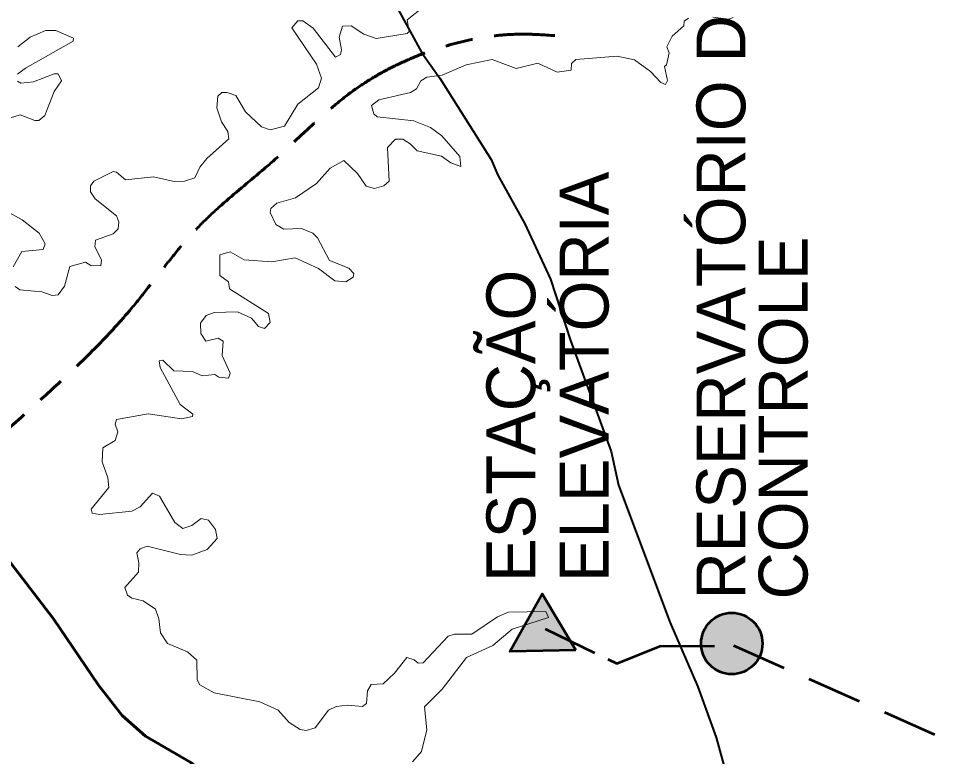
# Model space of a CAD drawing. Extents: x 553962 to 842807, y 8883888 to 9032388.
# Drawn here: x 584337 to 591881, y 8966488 to 8972533 of the extents above; entities that cross this region are included whole.
import ezdxf

# ---------------------------------------------------------------- set-up
doc = ezdxf.new("R2010")
doc.units = 0
doc.header["$LTSCALE"] = 150
doc.linetypes.add('LONG_DASH_SHORT_DASH', pattern=[9.9, 6, -1.2, 1.5, -1.2])
doc.linetypes.add('MEDIUM_DASHED', pattern=[4.5, 3, -1.5])
for name, color, linetype, lineweight in [('12', 7, 'Continuous', 25), ('25', 7, 'Continuous', 13), ('60', 7, 'Continuous', 53), ('7', 7, 'LONG_DASH_SHORT_DASH', 60)]:
    doc.layers.add(name, color=color, linetype=linetype, lineweight=lineweight)
doc.layers.add('50', color=7, linetype='Continuous')

msp = doc.modelspace()

# ---------------------------------------------------------------- hatches: boundary and pattern name
at = {"layer": '60'}
for points in [[(588902.6, 8967358.6), (588362.3, 8967350), (588625.1, 8967822.2)], [(590430, 8967414.1, 1), (589927.2, 8967414.1, 1)]]:
    msp.add_hatch(color=256, dxfattribs=at).paths.add_polyline_path(points)

# ---------------------------------------------------------------- linework, layer by layer
at = {"layer": '12', "lineweight": 40}
msp.add_lwpolyline([(587301, 8972874.3), (587640.4, 8972251.7), (587788.5, 8972042.4), (588207.4, 8971376.7), (588263.1, 8971248.8), (588483.5, 8970850.8), (588695.4, 8970396.6), (588857.5, 8969895.4), (589190.3, 8968987.7), (589251, 8968710.7), (589674.6, 8967582.3), (589899.5, 8967058.9), (590052.2, 8966645.4), (590154.6, 8966267.7), (590247.4, 8965995.5), (590238.8, 8965878.8), (590381.4, 8965077.2), (590437.7, 8964620.9), (590556.9, 8963909.5), (590712.3, 8962804.7), (590781.8, 8962609.4), (591396.4, 8961227.9)], dxfattribs=at)
at = {"layer": '25'}
for points in [[(585111.6, 8971279.2), (585141.3, 8971274.9), (585213.8, 8971211.3), (585443, 8971236.7), (585613.2, 8971196.4), (585698.2, 8971200.7), (585782.6, 8971228.1), (585821.2, 8971315.3), (585878.5, 8971385.4), (586058.9, 8971546.7), (586050.5, 8971606.3), (585999.6, 8971687.1), (585961.4, 8971801.8), (585969.8, 8971897.1), (586004, 8971925.1), (586046.1, 8971927.1), (586118.5, 8971901.5), (586197.3, 8971767.6), (586326.8, 8971644.7), (586399.8, 8971621.3), (586515.7, 8971651), (586626.4, 8971831.7), (586793.9, 8971963.1), (586819.5, 8972043.7), (586777.5, 8972158), (586575.5, 8972456.3), (586626.1, 8972513.3), (586666.5, 8972513.3), (586751.7, 8972453.7), (586934.4, 8972216.2), (586974.5, 8972237.3), (586982.9, 8972274.7), (586964.1, 8972379.9), (586989.7, 8972468.8), (587061.7, 8972470.9), (587164.3, 8972404.8), (587265.6, 8972369), (587521, 8972409.7), (587521, 8972409.7), (587537.4, 8972424.4), (587520.6, 8972519.8), (587652.2, 8972626)], [(585111.6, 8971279.2), (585141.3, 8971274.9), (585213.8, 8971211.3), (585443, 8971236.7), (585613.2, 8971196.4), (585698.2, 8971200.7), (585782.6, 8971228.1), (585821.2, 8971315.3), (585878.5, 8971385.4), (586058.9, 8971546.7), (586050.5, 8971606.3), (585999.6, 8971687.1), (585961.4, 8971801.8), (585969.8, 8971897.1), (586004, 8971925.1), (586046.1, 8971927.1), (586118.5, 8971901.5), (586197.3, 8971767.6), (586326.8, 8971644.7), (586399.8, 8971621.3), (586515.7, 8971651), (586626.4, 8971831.7), (586793.9, 8971963.1), (586819.5, 8972043.7), (586777.5, 8972158), (586575.5, 8972456.3), (586626.1, 8972513.3), (586666.5, 8972513.3), (586751.7, 8972453.7), (586934.4, 8972216.2), (586974.5, 8972237.3), (586982.9, 8972274.7), (586964.1, 8972379.9), (586989.7, 8972468.8), (587061.7, 8972470.9), (587164.3, 8972404.8), (587265.6, 8972369), (587521, 8972409.7), (587521, 8972409.7), (587537.4, 8972424.4), (587520.6, 8972519.8), (587652.2, 8972626)], [(589823.3, 8972534.6), (589789.5, 8972511.4), (589784.9, 8972471), (589689.6, 8972386.1), (589647, 8972301.2), (589666, 8972251.4), (589644.9, 8972152.7), (589627.8, 8972139.3), (589651.2, 8972025), (589636.7, 8971991.2), (589636.7, 8971991.2)], [(589823.3, 8972534.6), (589789.5, 8972511.4), (589784.9, 8972471), (589689.6, 8972386.1), (589647, 8972301.2), (589666, 8972251.4), (589644.9, 8972152.7), (589627.8, 8972139.3), (589651.2, 8972025), (589636.7, 8971991.2), (589636.7, 8971991.2)], [(590190.6, 8972539), (590153.7, 8972526.2), (590022.9, 8972543.1)], [(590190.6, 8972539), (590153.7, 8972526.2), (590022.9, 8972543.1)], [(584331.8, 8972301), (584432.1, 8972379.7), (584559.6, 8972432.7), (584559.6, 8972432.7), (584644.6, 8972432.6), (584786.6, 8972370.8), (584785.8, 8972347.3), (584395, 8972126.3), (584330, 8972075.8)], [(584331.8, 8972301), (584432.1, 8972379.7), (584559.6, 8972432.7), (584559.6, 8972432.7), (584644.6, 8972432.6), (584786.6, 8972370.8), (584785.8, 8972347.3), (584395, 8972126.3), (584330, 8972075.8)], [(589636.7, 8971991.2), (589598.1, 8972007.9), (589513.3, 8972099), (589381.6, 8972192.5), (589241.4, 8972224.5), (588901.3, 8972196.8), (588865.3, 8972162.9), (588863, 8972107.8), (588748.1, 8972092.9), (588748.1, 8972092.9), (588590.9, 8972165), (588412.8, 8972122.6), (588217.3, 8972196.9), (588004.9, 8972152.3), (587806, 8972067.6), (587682, 8972052.4), (587633.2, 8972022.7), (587596.9, 8971954.8), (587546.7, 8971925.3), (587289, 8971866.3), (587229.6, 8971820.7), (587248.6, 8971751), (587275.8, 8971727.9), (587576, 8971693.4), (587711.7, 8971638.2), (587803.3, 8971572.2), (587950.9, 8971402.7), (587960.4, 8971321.1)], [(589636.7, 8971991.2), (589598.1, 8972007.9), (589513.3, 8972099), (589381.6, 8972192.5), (589241.4, 8972224.5), (588901.3, 8972196.8), (588865.3, 8972162.9), (588863, 8972107.8), (588748.1, 8972092.9), (588748.1, 8972092.9), (588590.9, 8972165), (588412.8, 8972122.6), (588217.3, 8972196.9), (588004.9, 8972152.3), (587806, 8972067.6), (587682, 8972052.4), (587633.2, 8972022.7), (587596.9, 8971954.8), (587546.7, 8971925.3), (587289, 8971866.3), (587229.6, 8971820.7), (587248.6, 8971751), (587275.8, 8971727.9), (587576, 8971693.4), (587711.7, 8971638.2), (587803.3, 8971572.2), (587950.9, 8971402.7), (587960.4, 8971321.1)], [(584330, 8972018.8), (584357.8, 8972001.5), (584461.6, 8972014.2), (584630.9, 8972080), (584661.4, 8972077.8), (584690.8, 8972022.3), (584629.4, 8971933.2), (584552.9, 8971738.1), (584503.4, 8971697.7), (584472.4, 8971696.2), (584351.2, 8971742.2), (584236.4, 8971708.4)], [(584330, 8972018.8), (584357.8, 8972001.5), (584461.6, 8972014.2), (584630.9, 8972080), (584661.4, 8972077.8), (584690.8, 8972022.3), (584629.4, 8971933.2), (584552.9, 8971738.1), (584503.4, 8971697.7), (584472.4, 8971696.2), (584351.2, 8971742.2), (584236.4, 8971708.4)], [(587960.4, 8971321.1), (587960.4, 8971321.1), (587878.2, 8971348.9), (587800.7, 8971404.6), (587601.6, 8971447), (587546.2, 8971506.3), (587484.6, 8971544.6), (587424.8, 8971542.6), (587359.2, 8971474.4), (587373.9, 8971198.8), (587329.3, 8971162.4), (587253.1, 8971141.2), (587184.9, 8971158.2), (587112.5, 8971262.4), (587002, 8971368.3), (586889.7, 8971306.8), (586777.2, 8971181.7), (586606.9, 8971064.6), (586453.7, 8971019.6), (586403.3, 8970977.5), (586399, 8970942.1), (586445.6, 8970844.1), (586509.4, 8970807.7), (586653.8, 8970811.9), (586747.1, 8970773.8), (586785.6, 8970735.2), (586885.5, 8970550.7), (587042.4, 8970487), (587082.7, 8970444.8), (587078.6, 8970412.6), (587019.2, 8970376.5), (586928.2, 8970384.9), (586793.3, 8970485.2), (586602.9, 8970571.8), (586411.7, 8970540), (586184.3, 8970557.1), (586072, 8970620.6), (585986.8, 8970597.1), (585985.1, 8970426.9), (586057, 8970376.2), (586064.4, 8970318.2), (586383.6, 8970117.6), (586398.9, 8970043.2), (586352.2, 8969994.2), (586303.6, 8970008.9), (586245.3, 8970079.5), (586131.1, 8970130), (585940.1, 8970123.6), (585874.5, 8970100.3), (585827.6, 8970038.4), (585830, 8969952.9), (585872.2, 8969890), (585973.9, 8969915.4), (586012.3, 8969889.7), (586006, 8969772.9), (586071.7, 8969626.7), (586056.7, 8969586.3), (585978.4, 8969594.8), (585945.9, 8969618), (585842.4, 8969605.4), (585761.7, 8969641.4), (585609, 8969645.7), (585519.5, 8969734.8), (585490.3, 8969728.7), (585498.3, 8969673.3), (585661.4, 8969372.5), (585765.4, 8969291.4), (585763.8, 8969274.2), (585672.2, 8969254.8), (585400.5, 8969295.2), (585139.6, 8969248.4), (585128.7, 8969210.2), (585151.9, 8969146.5), (585128.6, 8969076.5), (585026.8, 8969016.8), (585022.1, 8968902.1), (585069.3, 8968771.8), (585077.6, 8968692.1), (584933.7, 8968514.1), (584939.8, 8968481.6), (585001.2, 8968471), (585266.9, 8968496.5), (585333.9, 8968534), (585434.5, 8968644.9), (585434.5, 8968644.9), (585492.3, 8968621), (585617.4, 8968405), (585683.3, 8968356.3), (585757.2, 8968379.6), (585833.8, 8968436.8), (585893.9, 8968423.6), (585950.2, 8968348.5), (585965.4, 8968274.1), (585883, 8968184.3), (585757.4, 8968137.5), (585664, 8968141.7), (585392.1, 8968211.7), (585332.8, 8968188.5), (585307.1, 8968156.3), (585324, 8968076.1), (585319.8, 8967999.4)], [(587960.4, 8971321.1), (587960.4, 8971321.1), (587878.2, 8971348.9), (587800.7, 8971404.6), (587601.6, 8971447), (587546.2, 8971506.3), (587484.6, 8971544.6), (587424.8, 8971542.6), (587359.2, 8971474.4), (587373.9, 8971198.8), (587329.3, 8971162.4), (587253.1, 8971141.2), (587184.9, 8971158.2), (587112.5, 8971262.4), (587002, 8971368.3), (586889.7, 8971306.8), (586777.2, 8971181.7), (586606.9, 8971064.6), (586453.7, 8971019.6), (586403.3, 8970977.5), (586399, 8970942.1), (586445.6, 8970844.1), (586509.4, 8970807.7), (586653.8, 8970811.9), (586747.1, 8970773.8), (586785.6, 8970735.2), (586885.5, 8970550.7), (587042.4, 8970487), (587082.7, 8970444.8), (587078.6, 8970412.6), (587019.2, 8970376.5), (586928.2, 8970384.9), (586793.3, 8970485.2), (586602.9, 8970571.8), (586411.7, 8970540), (586184.3, 8970557.1), (586072, 8970620.6), (585986.8, 8970597.1), (585985.1, 8970426.9), (586057, 8970376.2), (586064.4, 8970318.2), (586383.6, 8970117.6), (586398.9, 8970043.2), (586352.2, 8969994.2), (586303.6, 8970008.9), (586245.3, 8970079.5), (586131.1, 8970130), (585940.1, 8970123.6), (585874.5, 8970100.3), (585827.6, 8970038.4), (585830, 8969952.9), (585872.2, 8969890), (585973.9, 8969915.4), (586012.3, 8969889.7), (586006, 8969772.9), (586071.7, 8969626.7), (586056.7, 8969586.3), (585978.4, 8969594.8), (585945.9, 8969618), (585842.4, 8969605.4), (585761.7, 8969641.4), (585609, 8969645.7), (585519.5, 8969734.8), (585490.3, 8969728.7), (585498.3, 8969673.3), (585661.4, 8969372.5), (585765.4, 8969291.4), (585763.8, 8969274.2), (585672.2, 8969254.8), (585400.5, 8969295.2), (585139.6, 8969248.4), (585128.7, 8969210.2), (585151.9, 8969146.5), (585128.6, 8969076.5), (585026.8, 8969016.8), (585022.1, 8968902.1), (585069.3, 8968771.8), (585077.6, 8968692.1), (584933.7, 8968514.1), (584939.8, 8968481.6), (585001.2, 8968471), (585266.9, 8968496.5), (585333.9, 8968534), (585434.5, 8968644.9), (585434.5, 8968644.9), (585492.3, 8968621), (585617.4, 8968405), (585683.3, 8968356.3), (585757.2, 8968379.6), (585833.8, 8968436.8), (585893.9, 8968423.6), (585950.2, 8968348.5), (585965.4, 8968274.1), (585883, 8968184.3), (585757.4, 8968137.5), (585664, 8968141.7), (585392.1, 8968211.7), (585332.8, 8968188.5), (585307.1, 8968156.3), (585324, 8968076.1), (585319.8, 8967999.4)], [(584311, 8970338.1), (584347.1, 8970310.6), (584528.8, 8970293.7), (584614.4, 8970263.9), (584662.6, 8970267.9), (584714.5, 8970340.6), (584757.2, 8970501.8), (584885.6, 8970535.6), (584929, 8970508.2), (585011.6, 8970506.1), (585015.9, 8970557.2), (584963, 8970661.1), (584969.3, 8970716), (585111.8, 8970769.6), (585154, 8970809.8), (585158.3, 8970866.9), (585141.3, 8970915.8), (584965.3, 8971056), (584926.9, 8971113.6), (584926.9, 8971162.3), (584954.3, 8971200.4), (585111.6, 8971279.2)], [(584311, 8970338.1), (584347.1, 8970310.6), (584528.8, 8970293.7), (584614.4, 8970263.9), (584662.6, 8970267.9), (584714.5, 8970340.6), (584757.2, 8970501.8), (584885.6, 8970535.6), (584929, 8970508.2), (585011.6, 8970506.1), (585015.9, 8970557.2), (584963, 8970661.1), (584969.3, 8970716), (585111.8, 8970769.6), (585154, 8970809.8), (585158.3, 8970866.9), (585141.3, 8970915.8), (584965.3, 8971056), (584926.9, 8971113.6), (584926.9, 8971162.3), (584954.3, 8971200.4), (585111.6, 8971279.2)], [(584177.1, 8970988.3), (584368.2, 8970884.1), (584506.1, 8970773.8), (584557, 8970686.9), (584540.2, 8970639.9), (584364.7, 8970623), (584293.8, 8970497.2)], [(584177.1, 8970988.3), (584368.2, 8970884.1), (584506.1, 8970773.8), (584557, 8970686.9), (584540.2, 8970639.9), (584364.7, 8970623), (584293.8, 8970497.2)], [(585319.8, 8967999.4), (585209.4, 8967874), (585230.7, 8967810.4), (585264.6, 8967784.9), (585358.3, 8967763.5), (585460, 8967695.5), (585487.7, 8967616.8), (585500.5, 8967502.3), (585557.8, 8967413.1), (585721.3, 8967347.2), (585797.8, 8967276.9), (585799.9, 8967116.4), (585821.7, 8967075), (585940.4, 8967011.6), (586314, 8966937.2), (586464.8, 8966869.3), (586554.2, 8966767.2), (586645.4, 8966710), (586692.1, 8966701.5), (586766.2, 8966722.7), (586877, 8966869.2), (586938.3, 8966898.9), (587031.7, 8966909.6), (587155.3, 8966899.2), (587187, 8966922.6), (587195.6, 8967026.5), (587225.2, 8967079.4), (587325, 8967083.9), (587416.4, 8967171), (587516.5, 8967298.4), (587577.2, 8967281.7), (587609.8, 8967253.9), (587652.2, 8967256), (587856.2, 8967474.6), (587908.7, 8967491.8), (588049.3, 8967489.5), (588259.2, 8967631.5), (588349.7, 8967670.3), (588657.3, 8967677.5), (588667.8, 8967651.8)], [(585319.8, 8967999.4), (585209.4, 8967874), (585230.7, 8967810.4), (585264.6, 8967784.9), (585358.3, 8967763.5), (585460, 8967695.5), (585487.7, 8967616.8), (585500.5, 8967502.3), (585557.8, 8967413.1), (585721.3, 8967347.2), (585797.8, 8967276.9), (585799.9, 8967116.4), (585821.7, 8967075), (585940.4, 8967011.6), (586314, 8966937.2), (586464.8, 8966869.3), (586554.2, 8966767.2), (586645.4, 8966710), (586692.1, 8966701.5), (586766.2, 8966722.7), (586877, 8966869.2), (586938.3, 8966898.9), (587031.7, 8966909.6), (587155.3, 8966899.2), (587187, 8966922.6), (587195.6, 8967026.5), (587225.2, 8967079.4), (587325, 8967083.9), (587416.4, 8967171), (587516.5, 8967298.4), (587577.2, 8967281.7), (587609.8, 8967253.9), (587652.2, 8967256), (587856.2, 8967474.6), (587908.7, 8967491.8), (588049.3, 8967489.5), (588259.2, 8967631.5), (588349.7, 8967670.3), (588657.3, 8967677.5), (588667.8, 8967651.8)], [(588667.8, 8967651.8), (588678.2, 8967626.5), (588381.1, 8967532.1), (588221.7, 8967398.4), (588005.1, 8967300.6), (587807.3, 8967041.3), (587663.1, 8966894.9), (587682, 8966707.8), (587637.4, 8966529.4), (587563.2, 8966446.7)], [(588667.8, 8967651.8), (588678.2, 8967626.5), (588381.1, 8967532.1), (588221.7, 8967398.4), (588005.1, 8967300.6), (587807.3, 8967041.3), (587663.1, 8966894.9), (587682, 8966707.8), (587637.4, 8966529.4), (587563.2, 8966446.7)]]:
    msp.add_lwpolyline(points, dxfattribs=at)
at = {"layer": '60', "linetype": 'MEDIUM_DASHED'}
for p, q in [((588651.1, 8967535.2), (589157.2, 8967288)), ((590193.6, 8967396.9), (592045.8, 8966577.4))]:
    msp.add_line(p, q, dxfattribs=at)
at = {"layer": '60'}
msp.add_lwpolyline([(588902.6, 8967358.6), (588362.3, 8967350), (588625.1, 8967822.2)], close=True, dxfattribs=at)
at = {"layer": '60', "linetype": 'MEDIUM_DASHED'}
msp.add_lwpolyline([(589162.5, 8967285.3), (589236.5, 8967249.2), (589588.5, 8967391.6), (590147.3, 8967395.7)], dxfattribs=at)
at = {"layer": '60'}
msp.add_circle((590178.6, 8967414.1), 251.4, dxfattribs=at)
at = {"layer": '7'}
msp.add_lwpolyline([(583174.4, 8969966), (583327.9, 8969505.4), (583474.7, 8969160.4), (583725.5, 8968684.8), (583883.2, 8968539.9), (583982.9, 8968403.5), (584146.9, 8968235.1), (584624.8, 8967616.6), (584992.2, 8967072.1), (585186.8, 8966825.7), (585377.2, 8966655.9), (585748.8, 8966438.6), (585960.5, 8966257.3), (586351.6, 8965976.8), (586551, 8965796.4), (587006.6, 8965310.9), (587303.1, 8964815.2), (587426.7, 8964495.3)], dxfattribs=at)
msp.add_spline([(583719.8, 8968683.1), (584226, 8969147.1), (585263.8, 8970159.6), (585803.8, 8970817.7), (586453.4, 8971391.4), (587077.8, 8971939.8), (587744.3, 8972277.3), (588469.9, 8972403.9), (588728.8, 8972391.8)], degree=3, dxfattribs=at)

# ---------------------------------------------------------------- texts
at = {"layer": '50'}
for s, p in [('RESERVATÓRIO DE', (590289.9, 8967775.2)), ('ELEVATÓRIA', (589169.6, 8967918.6)), ('CONTROLE', (590799.2, 8967775.2)), ('ESTAÇÃO ', (588569.6, 8967918.6))]:
    msp.add_text(s, height=400, rotation=90, dxfattribs=at).set_placement(p)

doc.saveas('drawing.dxf')
